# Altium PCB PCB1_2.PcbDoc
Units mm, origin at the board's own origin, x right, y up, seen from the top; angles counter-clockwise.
Board outline 13.5 x 30 mm, 4 copper layers (Top Copper, Signal Layer 1, Signal Layer 2, Bottom Copper), stack 1.57 mm thick; 12 components, 9 nets, 40 pads, 24 vias.
Unrouted connection lines stored in the file: 1.
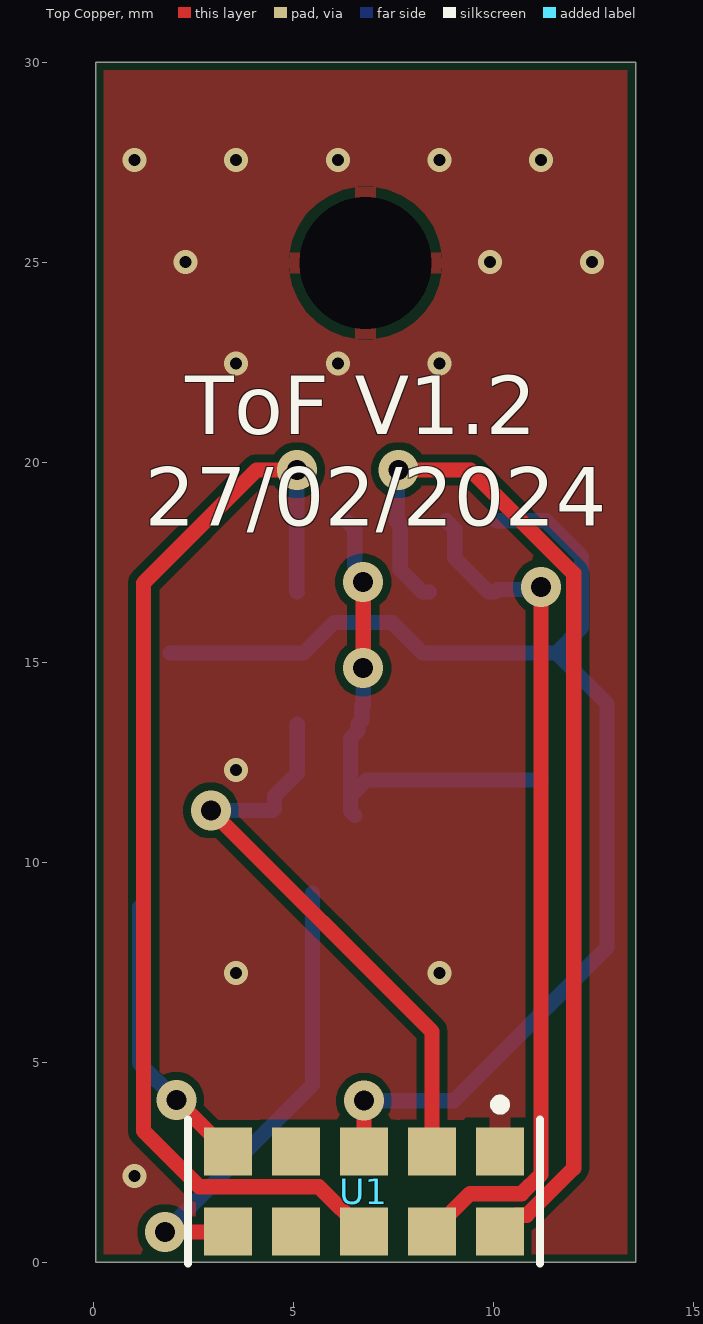
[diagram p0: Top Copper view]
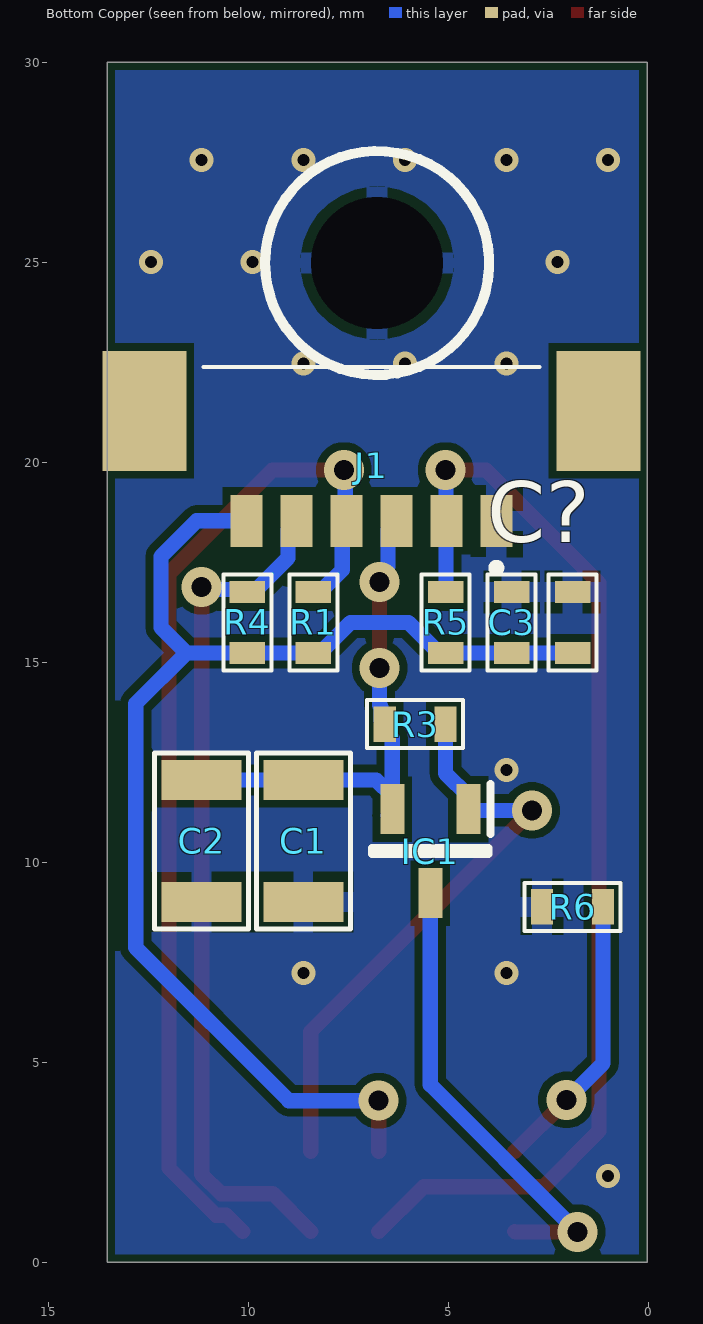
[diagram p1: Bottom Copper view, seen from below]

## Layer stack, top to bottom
Top Mask: solder mask 0.015, Solder Resist, Dk 3.8
Top Copper: signal copper 0.035
Dielectric 1: prepreg 0.2, 7628, Dk 4.6
Signal Layer 1: signal copper 0.0175
Core: core 1.065, FR-4, Dk 4.5
Signal Layer 2: signal copper 0.0175
Dielectric 2: prepreg 0.2, 7628, Dk 4.6
Bottom Copper: signal copper 0.035
Bottom Mask: solder mask 0.015, Solder Resist, Dk 3.8

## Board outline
0.041,0.005 13.541,0.005 13.541,30.005 0.041,30.005

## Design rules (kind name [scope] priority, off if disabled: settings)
BoardOutlineClearance [All] p1: gap=0.2 ignorepadtopadclearanceinfootprint=FALSE except(0.4: Arc-SplitBarrior Arc-SplitContinuation Track-SplitBarrior Track-SplitContinuation SMDPad-SplitBarrior SMDPad-SplitContinuation THPad-SplitBarrior THPad-SplitContinuation Via-SplitBarrior Via-SplitContinuation Fill-SplitBarrior Fill-SplitContinuation Poly-SplitBarrior Poly-SplitContinuation Region-SplitBarrior Region-SplitContinuation Text-SplitBarrior Text-SplitContinuation)
Clearance "Clearance Bottom Layer" [OnLayer('Bottom Layer')] p1: gap=0.203 ignorepadtopadclearanceinfootprint=TRUE except(0.254: Arc-Text Track-Text SMDPad-Text THPad-Text Via-Text Fill-Text Poly-Text Region-Text Text-Text)
Clearance "Clearance Top Layer" [OnLayer('Top Layer')] p2: gap=0.203 ignorepadtopadclearanceinfootprint=TRUE except(0.254: Arc-Text Track-Text SMDPad-Text THPad-Text Via-Text Fill-Text Poly-Text Region-Text Text-Text)
Clearance [All] p3: gap=0.2 ignorepadtopadclearanceinfootprint=FALSE except(0.089: Arc-Arc Arc-Track Arc-SMDPad Track-Track Track-SMDPad SMDPad-SMDPad; 0.127: Arc-Via Track-Via SMDPad-Via THPad-Via Via-Via; 0.254: Arc-Text Track-Text SMDPad-Text THPad-Text Via-Text Fill-Text Poly-Text Region-Text Text-Text)
HoleSize [All] p1: absolutevalues=TRUE maxlimit=6.3 minlimit=0.2 maxpercent=80.000 minpercent=20.000
MinimumAnnularRing [All] p1: minimumring=0.076
MinimumSolderMaskSliver [All] p1: minsoldermaskwidth=0.1
PolygonConnect PolygonConnect_1 [All] p1: thpad.connectstyle=Relief thpad.reliefconductorwidth=0.508 thpad.reliefentries=4 thpad.polygonreliefangle="90 Angle" thpad.airgapwidth=0.254 smdpad.connectstyle=Relief smdpad.reliefconductorwidth=0.508 smdpad.reliefentries=4 smdpad.polygonreliefangle="90 Angle" smdpad.airgapwidth=0.254 via.connectstyle=Direct via.reliefconductorwidth=0.508 via.reliefentries=4 via.polygonreliefangle="90 Angle" via.airgapwidth=0.254
RoutingCorners [All] p1: cornerstyle=Round minsetback=2.54 maxsetback=2.54
RoutingVias [All] p1: holewidth=0.5 width=1 viastyle="Through Hole" minholewidth=0.2 minwidth=0.45 maxholewidth=1 maxwidth=2
SilkToSilkClearance [All] p1: silktosilkclearance=0.1
SilkToSolderMaskClearance [IsPad] p1: minsilkscreentomaskgap=0.1 clearancetoexposedcopper=TRUE
SolderMaskExpansion [All] p1: expansion=0.102 istentingtop=FALSE
Width [All] p1: maxlimit=2.54 minlimit=0.089 preferedwidth=0.381
25 further rules are at their usual default settings.

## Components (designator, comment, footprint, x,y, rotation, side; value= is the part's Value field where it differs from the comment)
C1 "220µF" CAP_1206_1H90 8.636,10.541 r270 bottom
C2 "220µF" CAP_1206_1H90 11.176,10.541 r270 bottom
C3 "0.1µF" CAP_0603_0H80 3.429,16.002 r270 bottom
C? "47uF" CAP_0603_0H80 1.905,16.002 r270 bottom
IC1 "SI2301BDS-T1-E3" SOT95P237X112-3N 5.461,10.287 r270 bottom
J1 "53398-0671" 533980671 6.935,20.467 r180 bottom
R1 "2.2k" RES_0603_0H90_2 8.382,16.002 r270 bottom
R3 "1k" RES_0603_0H90_2 5.842,13.462 r0 bottom
R4 "2.2k" RES_0603_0H90_2 10.033,16.002 r270 bottom
R5 "8.2k" RES_0603_0H90_2 5.08,16.002 r270 bottom
R6 "2.7R" RES_0603_0H90_2 1.905,8.89 r180 bottom
U1 "VCNL4200" FP-VCNL4200-MFG 6.75,1.773 r180 top

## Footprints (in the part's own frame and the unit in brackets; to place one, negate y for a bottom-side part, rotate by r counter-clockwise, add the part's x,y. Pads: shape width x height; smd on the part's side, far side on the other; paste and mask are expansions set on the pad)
533980671 [mm]
  rect 0.8x1.3 smd: 1(3.125,-1.925) 2(1.875,-1.925) 3(0.625,-1.925) 4(-0.625,-1.925) 5(-1.875,-1.925) 6(-3.125,-1.925)
  rect 2.1x3 smd: MP1(-5.675,0.825) MP2(5.675,0.825)
  silkscreen extent -4.2,-3.2 4.2,1.93, body extent -6.32,-2.54 6.32,1.66, height 4.7
CAP_0603_0H80 [mil] "refusion"
  rect 22x35 smd: 1(-30,0) 2(30,0)
  silkscreen extent -47,-24 47,24, body extent -31,-16 31,16, height 31
CAP_1206_1H90 [mm] "refusion"
  rect 1x2 smd paste+0 mask+0.1: 1(-1.524,0) 2(1.524,0)
  silkscreen extent -2.2,-1.17 2.2,1.17, body extent -1.6,-0.8 1.6,0.8, height 1.9
FP-VCNL4200-MFG [mm]
  rect 1.2x1.2 smd paste+0 mask+0: 1(-3.4,-1) 2(-1.7,-1) 3(0,-1) 4(1.7,-1) 5(3.4,-1) 6(3.4,1) 7(1.7,1) 8(0,1) 9(-1.7,1) 10(-3.4,1)
  silkscreen extent -4.4,-2.3 4.4,1.8, body extent -4.15,-1.7 4.15,1.7, height 0.25
RES_0603_0H90_2 [mil]
  rect 22x35 smd: 1(-30,0) 2(30,0)
  silkscreen extent -47,-24 47,24, body extent -31,-16 31,16, height 35
SOT95P237X112-3N [mm]
  rect 1.25x0.6 smd: 1(-1.05,0.95) 2(-1.05,-0.95) 3(1.05,0)
  silkscreen extent -1.67,-1.46 0.07,1.5, body extent -1.27,-1.46 1.27,1.46, height 1

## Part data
C1: library part C0603-10µF-X5R-6.3V, "Capacitor, Ceramic, 220µF, 1206, 10%, 6.3V, X5R", CASE=1206, Dielectric=X5R, Voltage=6.3V
C2: library part C0603-10µF-X5R-6.3V, "Capacitor, Ceramic, 220µF, 0603, 10%, 6.3V, X5R", CASE=1206, Dielectric=X5R, Voltage=6.3V
C3: library part C0603-10µF-X5R-6.3V, "Capacitor, Ceramic, 0.1µF, 0603, 10%, 6.3V, X5R", CASE=0603, Dielectric=X5R, Voltage=6.3V
C?: library part C0603-10µF-X5R-6.3V, "Capacitor, Ceramic, 47µF, 0603, 10%, 6.3V, X5R", CASE=0603, Dielectric=X5R, Voltage=6.3V
IC1: "Integrated Circuit", Manufacturer_Name=Vishay, Mouser Part Number=781-SI2301BDS-E3
J1: "Connector", Manufacturer_Name=Molex, Mouser Part Number=538-53398-0671
R1 R4: library part R0603_120k_1%, "Resistor, Thin Film, 2.2k, 1%, 65mW, 0603", CASE=0603, Power=65mW, Tolerance=1%
R3: library part R0603_120k_1%, "Resistor, Thin Film, 1k, 1%, 65mW, 0603", CASE=0603, Power=65mW, Tolerance=1%
R5: library part R0603_120k_1%, "Resistor, Thin Film, 8.2k, 1%, 65mW, 0603", CASE=0603, Power=65mW, Tolerance=1%
R6: library part R0603_120k_1%, "Resistor, Thin Film, 2.7R, 1%, 65mW, 0603", CASE=0603, Power=65mW, Tolerance=1%
U1: library part CMP-02530-000006-1, "SENSOR OPT 550NM AMBIENT 10SMD", Ambient Temperature Range High=+85°C, Ambient Temperature Range Low=-40°C, Manufacturer=Vishay, Max Supply Voltage=3.6V, Min Supply Voltage=2.5V, Operating Supply Current=350uA, Package=0, Temperature="-40°C to +85°C"

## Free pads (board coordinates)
  round 1.524 hole 3.3 unplated: Pad1(6.791,24.988)

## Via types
v1: diameter 0.6, hole 0.3, Top Copper to Bottom Copper, tented both sides, 15 vias
v2: diameter 1, hole 0.5, Top Copper to Bottom Copper, tented both sides, 9 vias

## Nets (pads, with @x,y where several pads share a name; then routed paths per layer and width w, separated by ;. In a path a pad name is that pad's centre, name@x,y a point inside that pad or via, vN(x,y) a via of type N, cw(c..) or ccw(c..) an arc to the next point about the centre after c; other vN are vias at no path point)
3V3: C3.2 C?.2 J1.6 R1.2 R4.2 R5.2 U1.3 | length 32.3
  Top Copper w0.381: U1.3 v2(6.75,4.045)
  Bottom Copper w0.381: C?.2 C3.2 R5.2 5.245,15.24 6.007,16.002 7.455,16.002 8.217,15.24 R1.2 R4.2 11.557,15.24 ; v2(6.75,4.045) 8.998,4.045 12.827,7.874 12.827,13.97 11.557,15.24 ; J1.6 11.303,18.542 12.192,17.653 12.192,15.875 11.557,15.24
5V: C1.1 C2.1 IC1.2 J1.3 R3.2 | length 12.2
  Top Copper w0.381: v2(6.731,14.859) v2(6.731,17.018)
  Bottom Copper w0.381: J1.3 6.52,18.332 v2@6.52,17.397 ; IC1.2@6.521,11.176 6.411,11.285 IC1.2 IC1.2@6.411,11.662 ; v2(6.731,14.859) 6.731,13.932 6.693,13.894 6.693,13.551 R3.2 6.604,13.297 6.411,13.104 IC1.2@6.411,11.662 ; C2.1 C1.1 6.814,12.065 IC1.2@6.411,11.662
GND: C1.2 C2.2 C3.1 C?.1 J1.1 pad.Pad1 R6.1 U1.1
  other v1: 1.016,2.159 3.556,7.239 8.636,7.239 3.556,12.319 3.556,22.479 6.096,22.479 8.636,22.479 2.286,25.019 9.906,25.019 12.446,25.019 1.016,27.559 3.556,27.559 6.096,27.559 8.636,27.559 11.176,27.559
INT: J1.2 R5.1 U1.8 | length 28.3
  Top Copper w0.381: v2(5.08,19.812) 4.064,19.812 1.242,16.99 1.242,3.286 2.634,1.894 5.629,1.894 U1.8
  Bottom Copper w0.381: R5.1 5.07,16.774 5.07,18.532 J1.2 5.07,18.552 5.07,19.802 v2(5.08,19.812)
NetIC1_1: IC1.1 R3.1 U1.2 | length 14.8
  Top Copper w0.381: v2(2.921,11.303) 8.45,5.774 U1.2
  Bottom Copper w0.381: v2(2.921,11.303) 4.477,11.303 IC1.1 4.511,11.662 5.08,12.231 R3.1
NetIC1_3: IC1.3 U1.6 | length 11.6
  Top Copper w0.381: v2(1.778,0.762) 3.339,0.762 U1.6
  Bottom Copper w0.381: v2(1.778,0.762) 5.461,4.445 IC1.3
NetR6_2: R6.2 U1.5 | length 7
  Top Copper w0.381: v2(2.059,4.064) U1.5
  Bottom Copper w0.381: R6.2 1.143,4.98 v2(2.059,4.064)
SCL: J1.4 R1.1 U1.10 | length 26.3
  Top Copper w0.381: v2(7.62,19.812) 9.411,19.812 11.994,17.23 11.994,2.357 10.819,1.183 10.559,1.183 U1.10
  Bottom Copper w0.381: v2(7.62,19.812) 7.59,19.782 7.59,18.572 J1.4 7.66,18.442 7.66,17.32 8.217,16.764 R1.1
SDA: J1.5 R4.1 U1.9 | length 21.6
  Top Copper w0.381: U1.9 9.398,1.721 10.693,1.721 11.176,2.204 v2(11.176,16.891)
  Bottom Copper w0.381: J1.5 9.019,18.332 9.019,17.612 9.868,16.764 R4.1 10.096,16.828 11.112,16.828 v2(11.176,16.891)
pads on no net: J1.MP1 J1.MP2 U1.4 U1.7

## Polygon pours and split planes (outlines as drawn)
GND on Top Copper "GND_L01_P001" (solid, pour order 1): -0.889,-1.524 -0.889,34.29 -1.651,35.052 0.254,36.957 13.843,36.957 14.478,36.322 14.097,35.941 14.097,-0.381
GND on Bottom Copper "GND_L04_P000" (solid, pour order 0): -1.905,-0.762 -1.651,-0.508 -1.651,37.719 14.097,37.719 14.605,37.211 14.605,-1.905

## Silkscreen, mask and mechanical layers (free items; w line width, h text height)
Top Overlay:
  text "ToF V1.2" at 2.286,20.218 h2.5
  text "27/02/2024" at 1.268,17.935 h2.5
Bottom Overlay:
  circle w0.254: c6.791,24.988 r2.8
Mechanical 1:
  circle w0.013: c6.791,24.988 r1.6
  circle w0.013: c9.191,1.778 r1.027
  circle w0.013: c4.191,1.778 r0.853
  circle w0.013: c9.191,1.778 r1.027
  circle w0.013: c4.191,1.778 r0.853
  lines w0.013: 3.097,0.412 10.485,0.412 ; 3.097,0.412 3.097,3.144 ; 3.097,0.412 3.097,3.144 ; 3.097,0.412 10.485,0.412 ; 3.097,3.144 10.485,3.144 ; 3.097,3.144 10.485,3.144 ; 10.485,0.412 10.485,3.144 ; 10.485,0.412 10.485,3.144 ; 0.041,0.005 0.041,30.005 13.541,30.005 13.541,0.005 0.041,0.005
